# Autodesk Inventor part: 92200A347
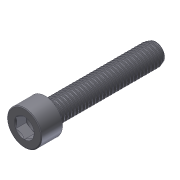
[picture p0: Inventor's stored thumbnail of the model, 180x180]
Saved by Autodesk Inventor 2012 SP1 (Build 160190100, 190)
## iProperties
Created: 2012-03
Part Number: 92200A347
Material: Stainless Steel
Document SubType Name: Modeling
Designer: jdh
Mass: 4.85594 g
Surface Area: 7.78252 cm^2
Volume: 0.600983 cm^3
Density: 8.08 g/cm^3
Author: jdh
Translation Standard: STEP AP203
FileName: 92200A347.step
PreProcessor: SolidWorks 2003314
PostProcessor: Build: 190, Release: 2012 SP1 - Date: Mon 08/08/2011
Sent Units: inch
Uncertainty: 1e-05
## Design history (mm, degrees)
node "92200A3471"
node "NONE"
node "Base1"
